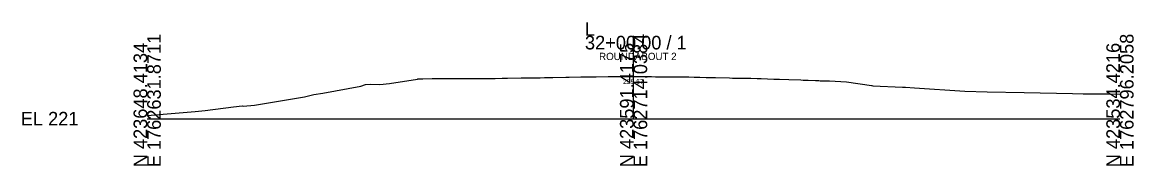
# Model space of a CAD drawing. Extents: x -26 to 3203, y -11010 to 4024.
# Drawn here: x 974.3 to 1202.8, y -3009.7 to -2980.1 of the extents above; entities that cross this region are included whole.
import ezdxf

# ---------------------------------------------------------------- set-up
doc = ezdxf.new("R2010")
doc.units = 0
for name, color, linetype in [('Default', 7, 'Continuous'), ('Exist Cross Section Cell', 7, 'Continuous'), ('Exist XS Center Line Elevation Label', 7, 'Continuous'), ('Exist XS Ground Line', 7, 'Continuous'), ('Prop XS SE Text', 7, 'Continuous')]:
    doc.layers.add(name, color=color, linetype=linetype)

msp = doc.modelspace()

# ---------------------------------------------------------------- linework, layer by layer
at = {"layer": 'Exist Cross Section Cell'}
for p, q in [((1100, -3000), (1100, -2982.95)), ((1000, -3000), (1100, -3000)), ((1100, -3000), (1200, -3000))]:
    msp.add_line(p, q, dxfattribs=at)
at = {"layer": 'Exist XS Ground Line'}
msp.add_lwpolyline([(1000, -2999.32), (1009.89, -2998.55), (1011.89, -2998.34), (1017.75, -2997.59), (1019.55, -2997.35), (1019.72, -2997.44), (1022.06, -2997.21), (1032.31, -2995.53), (1034.23, -2995.04), (1036.12, -2994.75), (1043.89, -2993.34), (1044.91, -2992.97), (1045.93, -2992.89), (1047.82, -2992.94), (1049.85, -2992.74), (1055.59, -2991.84), (1055.61, -2991.82), (1055.64, -2991.82), (1055.83, -2991.81), (1056.18, -2991.79), (1056.69, -2991.79), (1058.59, -2991.76), (1059.08, -2991.76), (1059.14, -2991.76), (1059.72, -2991.75), (1061.04, -2991.75), (1061.93, -2991.74), (1062.83, -2991.74), (1064.17, -2991.74), (1064.98, -2991.74), (1066.77, -2991.73), (1068, -2991.73), (1068.23, -2991.73), (1068.55, -2991.73), (1070.73, -2991.72), (1071.21, -2991.72), (1071.53, -2991.71), (1072.99, -2991.68), (1074.08, -2991.66), (1076.92, -2991.61), (1077.21, -2991.61), (1077.33, -2991.61), (1080.13, -2991.58), (1080.79, -2991.57), (1081.68, -2991.55), (1082.7, -2991.53), (1082.93, -2991.53), (1083.41, -2991.52), (1086.04, -2991.48), (1086.19, -2991.48), (1086.29, -2991.48), (1086.77, -2991.47), (1089.19, -2991.42), (1089.69, -2991.41), (1090.45, -2991.4), (1091.58, -2991.38), (1092.31, -2991.37), (1094.76, -2991.33), (1095.1, -2991.33), (1095.36, -2991.33), (1096.93, -2991.33), (1098.46, -2991.33), (1099.27, -2991.33), (1101.49, -2991.34), (1102.34, -2991.34), (1103.68, -2991.35), (1104.54, -2991.36), (1106.64, -2991.38), (1107.63, -2991.4), (1107.81, -2991.4), (1108.04, -2991.4), (1110.62, -2991.42), (1111.36, -2991.42), (1112.45, -2991.44), (1113.63, -2991.46), (1114.9, -2991.5), (1116.72, -2991.53), (1116.86, -2991.53), (1119.73, -2991.62), (1120.32, -2991.64), (1121.16, -2991.66), (1122.07, -2991.68), (1122.71, -2991.69), (1123.52, -2991.69), (1124.09, -2991.69), (1124.1, -2991.69), (1125.39, -2991.73), (1125.74, -2991.75), (1125.81, -2991.75), (1126.22, -2991.76), (1128.82, -2991.85), (1129.28, -2991.87), (1129.99, -2991.89), (1131.91, -2991.95), (1134.37, -2992.04), (1134.88, -2992.06), (1135.92, -2992.09), (1137.42, -2992.14), (1137.72, -2992.15), (1138.07, -2992.17), (1138.39, -2992.19), (1140.25, -2992.23), (1143.77, -2992.41), (1148.95, -2993.19), (1148.96, -2993.19), (1148.99, -2993.2), (1149.18, -2993.22), (1155.27, -2993.53), (1155.94, -2993.5), (1157.78, -2993.63), (1168.11, -2994.35), (1172.67, -2994.48), (1180.28, -2994.62), (1190.21, -2994.84), (1192.45, -2994.89), (1197.51, -2994.92), (1200, -2994.93)], dxfattribs=at)
msp.add_lwpolyline([(1000, -2999.32), (1009.89, -2998.55), (1011.89, -2998.34), (1017.75, -2997.59), (1019.55, -2997.35), (1019.72, -2997.44), (1022.06, -2997.21), (1032.31, -2995.53), (1034.23, -2995.04), (1036.12, -2994.75), (1043.89, -2993.34), (1044.91, -2992.97), (1045.93, -2992.89), (1047.82, -2992.94), (1049.85, -2992.74), (1055.59, -2991.84), (1055.61, -2991.82), (1055.64, -2991.82), (1055.83, -2991.81), (1056.18, -2991.79), (1056.69, -2991.79), (1058.59, -2991.76), (1059.08, -2991.76), (1059.14, -2991.76), (1059.72, -2991.75), (1061.04, -2991.75), (1061.93, -2991.74), (1062.83, -2991.74), (1064.17, -2991.74), (1064.98, -2991.74), (1066.77, -2991.73), (1068, -2991.73), (1068.23, -2991.73), (1068.55, -2991.73), (1070.73, -2991.72), (1071.21, -2991.72), (1071.53, -2991.71), (1072.99, -2991.68), (1074.08, -2991.66), (1076.92, -2991.61), (1077.21, -2991.61), (1077.33, -2991.61), (1080.13, -2991.58), (1080.79, -2991.57), (1081.68, -2991.55), (1082.7, -2991.53), (1082.93, -2991.53), (1083.41, -2991.52), (1086.04, -2991.48), (1086.19, -2991.48), (1086.29, -2991.48), (1086.77, -2991.47), (1089.19, -2991.42), (1089.69, -2991.41), (1090.45, -2991.4), (1091.58, -2991.38), (1092.31, -2991.37), (1094.76, -2991.33), (1095.1, -2991.33), (1095.36, -2991.33), (1096.93, -2991.33), (1098.46, -2991.33), (1099.27, -2991.33), (1101.49, -2991.34), (1102.34, -2991.34), (1103.68, -2991.35), (1104.54, -2991.36), (1106.64, -2991.38), (1107.63, -2991.4), (1107.81, -2991.4), (1108.04, -2991.4), (1110.62, -2991.42), (1111.36, -2991.42), (1112.45, -2991.44), (1113.63, -2991.46), (1114.9, -2991.5), (1116.72, -2991.53), (1116.86, -2991.53), (1119.73, -2991.62), (1120.32, -2991.64), (1121.16, -2991.66), (1122.07, -2991.68), (1122.71, -2991.69), (1123.52, -2991.69), (1124.09, -2991.69), (1124.1, -2991.69), (1125.39, -2991.73), (1125.74, -2991.75), (1125.81, -2991.75), (1126.22, -2991.76), (1128.82, -2991.85), (1129.28, -2991.87), (1129.99, -2991.89), (1131.91, -2991.95), (1134.37, -2992.04), (1134.88, -2992.06), (1135.92, -2992.09), (1137.42, -2992.14), (1137.72, -2992.15), (1138.07, -2992.17), (1138.39, -2992.19), (1140.25, -2992.23), (1143.77, -2992.41), (1148.95, -2993.19), (1148.96, -2993.19), (1148.99, -2993.2), (1149.18, -2993.22), (1155.27, -2993.53), (1155.94, -2993.5), (1157.78, -2993.63), (1168.11, -2994.35), (1172.67, -2994.48), (1180.28, -2994.62), (1190.21, -2994.84), (1192.45, -2994.89), (1197.51, -2994.92), (1200, -2994.93)], dxfattribs=at)
msp.add_lwpolyline([(1000, -2999.32), (1009.89, -2998.55), (1011.89, -2998.34), (1017.75, -2997.59), (1019.55, -2997.35), (1019.72, -2997.44), (1022.06, -2997.21), (1032.31, -2995.53), (1034.23, -2995.04), (1036.12, -2994.75), (1043.89, -2993.34), (1044.91, -2992.97), (1045.93, -2992.89), (1047.82, -2992.94), (1049.85, -2992.74), (1055.59, -2991.84), (1055.61, -2991.82), (1055.64, -2991.82), (1055.83, -2991.81), (1056.18, -2991.79), (1056.69, -2991.79), (1058.59, -2991.76), (1059.08, -2991.76), (1059.14, -2991.76), (1059.72, -2991.75), (1061.04, -2991.75), (1061.93, -2991.74), (1062.83, -2991.74), (1064.17, -2991.74), (1064.98, -2991.74), (1066.77, -2991.73), (1068, -2991.73), (1068.23, -2991.73), (1068.55, -2991.73), (1070.73, -2991.72), (1071.21, -2991.72), (1071.53, -2991.71), (1072.99, -2991.68), (1074.08, -2991.66), (1076.92, -2991.61), (1077.21, -2991.61), (1077.33, -2991.61), (1080.13, -2991.58), (1080.79, -2991.57), (1081.68, -2991.55), (1082.7, -2991.53), (1082.93, -2991.53), (1083.41, -2991.52), (1086.04, -2991.48), (1086.19, -2991.48), (1086.29, -2991.48), (1086.77, -2991.47), (1089.19, -2991.42), (1089.69, -2991.41), (1090.45, -2991.4), (1091.58, -2991.38), (1092.31, -2991.37), (1094.76, -2991.33), (1095.1, -2991.33), (1095.36, -2991.33), (1096.93, -2991.33), (1098.46, -2991.33), (1099.27, -2991.33), (1101.49, -2991.34), (1102.34, -2991.34), (1103.68, -2991.35), (1104.54, -2991.36), (1106.64, -2991.38), (1107.63, -2991.4), (1107.81, -2991.4), (1108.04, -2991.4), (1110.62, -2991.42), (1111.36, -2991.42), (1112.45, -2991.44), (1113.63, -2991.46), (1114.9, -2991.5), (1116.72, -2991.53), (1116.86, -2991.53), (1119.73, -2991.62), (1120.32, -2991.64), (1121.16, -2991.66), (1122.07, -2991.68), (1122.71, -2991.69), (1123.52, -2991.69), (1124.09, -2991.69), (1124.1, -2991.69), (1125.39, -2991.73), (1125.74, -2991.75), (1125.81, -2991.75), (1126.22, -2991.76), (1128.82, -2991.85), (1129.28, -2991.87), (1129.99, -2991.89), (1131.91, -2991.95), (1134.37, -2992.04), (1134.88, -2992.06), (1135.92, -2992.09), (1137.42, -2992.14), (1137.72, -2992.15), (1138.07, -2992.17), (1138.39, -2992.19), (1140.25, -2992.23), (1143.77, -2992.41), (1148.95, -2993.19), (1148.96, -2993.19), (1148.99, -2993.2), (1149.18, -2993.22), (1155.27, -2993.53), (1155.94, -2993.5), (1157.78, -2993.63), (1168.11, -2994.35), (1172.67, -2994.48), (1180.28, -2994.62), (1190.21, -2994.84), (1192.45, -2994.89), (1197.51, -2994.92), (1200, -2994.93)], dxfattribs=at)
msp.add_lwpolyline([(1000, -2999.32), (1009.89, -2998.55), (1011.89, -2998.34), (1017.75, -2997.59), (1019.55, -2997.35), (1019.72, -2997.44), (1022.06, -2997.21), (1032.31, -2995.53), (1034.23, -2995.04), (1036.12, -2994.75), (1043.89, -2993.34), (1044.91, -2992.97), (1045.93, -2992.89), (1047.82, -2992.94), (1049.85, -2992.74), (1055.59, -2991.84), (1055.61, -2991.82), (1055.64, -2991.82), (1055.83, -2991.81), (1056.18, -2991.79), (1056.69, -2991.79), (1058.59, -2991.76), (1059.08, -2991.76), (1059.14, -2991.76), (1059.72, -2991.75), (1061.04, -2991.75), (1061.93, -2991.74), (1062.83, -2991.74), (1064.17, -2991.74), (1064.98, -2991.74), (1066.77, -2991.73), (1068, -2991.73), (1068.23, -2991.73), (1068.55, -2991.73), (1070.73, -2991.72), (1071.21, -2991.72), (1071.53, -2991.71), (1072.99, -2991.68), (1074.08, -2991.66), (1076.92, -2991.61), (1077.21, -2991.61), (1077.33, -2991.61), (1080.13, -2991.58), (1080.79, -2991.57), (1081.68, -2991.55), (1082.7, -2991.53), (1082.93, -2991.53), (1083.41, -2991.52), (1086.04, -2991.48), (1086.19, -2991.48), (1086.29, -2991.48), (1086.77, -2991.47), (1089.19, -2991.42), (1089.69, -2991.41), (1090.45, -2991.4), (1091.58, -2991.38), (1092.31, -2991.37), (1094.76, -2991.33), (1095.1, -2991.33), (1095.36, -2991.33), (1096.93, -2991.33), (1098.46, -2991.33), (1099.27, -2991.33), (1101.49, -2991.34), (1102.34, -2991.34), (1103.68, -2991.35), (1104.54, -2991.36), (1106.64, -2991.38), (1107.63, -2991.4), (1107.81, -2991.4), (1108.04, -2991.4), (1110.62, -2991.42), (1111.36, -2991.42), (1112.45, -2991.44), (1113.63, -2991.46), (1114.9, -2991.5), (1116.72, -2991.53), (1116.86, -2991.53), (1119.73, -2991.62), (1120.32, -2991.64), (1121.16, -2991.66), (1122.07, -2991.68), (1122.71, -2991.69), (1123.52, -2991.69), (1124.09, -2991.69), (1124.1, -2991.69), (1125.39, -2991.73), (1125.74, -2991.75), (1125.81, -2991.75), (1126.22, -2991.76), (1128.82, -2991.85), (1129.28, -2991.87), (1129.99, -2991.89), (1131.91, -2991.95), (1134.37, -2992.04), (1134.88, -2992.06), (1135.92, -2992.09), (1137.42, -2992.14), (1137.72, -2992.15), (1138.07, -2992.17), (1138.39, -2992.19), (1140.25, -2992.23), (1143.77, -2992.41), (1148.95, -2993.19), (1148.96, -2993.19), (1148.99, -2993.2), (1149.18, -2993.22), (1155.27, -2993.53), (1155.94, -2993.5), (1157.78, -2993.63), (1168.11, -2994.35), (1172.67, -2994.48), (1180.28, -2994.62), (1190.21, -2994.84), (1192.45, -2994.89), (1197.51, -2994.92), (1200, -2994.93)], dxfattribs=at)
msp.add_lwpolyline([(1000, -2999.32), (1009.89, -2998.55), (1011.89, -2998.34), (1017.75, -2997.59), (1019.55, -2997.35), (1019.72, -2997.44), (1022.06, -2997.21), (1032.31, -2995.53), (1034.23, -2995.04), (1036.12, -2994.75), (1043.89, -2993.34), (1044.91, -2992.97), (1045.93, -2992.89), (1047.82, -2992.94), (1049.85, -2992.74), (1055.59, -2991.84), (1055.61, -2991.82), (1055.64, -2991.82), (1055.83, -2991.81), (1056.18, -2991.79), (1056.69, -2991.79), (1058.59, -2991.76), (1059.08, -2991.76), (1059.14, -2991.76), (1059.72, -2991.75), (1061.04, -2991.75), (1061.93, -2991.74), (1062.83, -2991.74), (1064.17, -2991.74), (1064.98, -2991.74), (1066.77, -2991.73), (1068, -2991.73), (1068.23, -2991.73), (1068.55, -2991.73), (1070.73, -2991.72), (1071.21, -2991.72), (1071.53, -2991.71), (1072.99, -2991.68), (1074.08, -2991.66), (1076.92, -2991.61), (1077.21, -2991.61), (1077.33, -2991.61), (1080.13, -2991.58), (1080.79, -2991.57), (1081.68, -2991.55), (1082.7, -2991.53), (1082.93, -2991.53), (1083.41, -2991.52), (1086.04, -2991.48), (1086.19, -2991.48), (1086.29, -2991.48), (1086.77, -2991.47), (1089.19, -2991.42), (1089.69, -2991.41), (1090.45, -2991.4), (1091.58, -2991.38), (1092.31, -2991.37), (1094.76, -2991.33), (1095.1, -2991.33), (1095.36, -2991.33), (1096.93, -2991.33), (1098.46, -2991.33), (1099.27, -2991.33), (1101.49, -2991.34), (1102.34, -2991.34), (1103.68, -2991.35), (1104.54, -2991.36), (1106.64, -2991.38), (1107.63, -2991.4), (1107.81, -2991.4), (1108.04, -2991.4), (1110.62, -2991.42), (1111.36, -2991.42), (1112.45, -2991.44), (1113.63, -2991.46), (1114.9, -2991.5), (1116.72, -2991.53), (1116.86, -2991.53), (1119.73, -2991.62), (1120.32, -2991.64), (1121.16, -2991.66), (1122.07, -2991.68), (1122.71, -2991.69), (1123.52, -2991.69), (1124.09, -2991.69), (1124.1, -2991.69), (1125.39, -2991.73), (1125.74, -2991.75), (1125.81, -2991.75), (1126.22, -2991.76), (1128.82, -2991.85), (1129.28, -2991.87), (1129.99, -2991.89), (1131.91, -2991.95), (1134.37, -2992.04), (1134.88, -2992.06), (1135.92, -2992.09), (1137.42, -2992.14), (1137.72, -2992.15), (1138.07, -2992.17), (1138.39, -2992.19), (1140.25, -2992.23), (1143.77, -2992.41), (1148.95, -2993.19), (1148.96, -2993.19), (1148.99, -2993.2), (1149.18, -2993.22), (1155.27, -2993.53), (1155.94, -2993.5), (1157.78, -2993.63), (1168.11, -2994.35), (1172.67, -2994.48), (1180.28, -2994.62), (1190.21, -2994.84), (1192.45, -2994.89), (1197.51, -2994.92), (1200, -2994.93)], dxfattribs=at)

# ---------------------------------------------------------------- texts
at = {"layer": 'Default'}
msp.add_text('-', height=0.0001, dxfattribs=at).set_placement((1000, -3000))
msp.add_text('-', height=0.0001, dxfattribs=at).set_placement((1000, -3000))
at = {"layer": 'Exist Cross Section Cell'}
for s, p in [('L', (1090, -2982.95)), ('32+00.00 / 1', (1090, -2985.75)), ('EL 221', (974, -3001.4))]:
    msp.add_text(s, height=2.8, dxfattribs=at).set_placement(p)
for s, p in [('N 423648.4134', (1000, -3010)), ('E 1762631.8711', (1002.8, -3010)), ('N 423591.4175', (1100, -3010)), ('E 1762714.0384', (1102.8, -3010)), ('N 423534.4216', (1200, -3010)), ('E 1762796.2058', (1202.8, -3010))]:
    msp.add_text(s, height=2.8, rotation=90, dxfattribs=at).set_placement(p)
at = {"layer": 'Exist XS Center Line Elevation Label'}
msp.add_text('229.67', height=1, dxfattribs=at).set_placement((1097.85, -2992.83))
at = {"layer": 'Prop XS SE Text'}
msp.add_text('ROUNDABOUT 2', height=1.5, rotation=360, dxfattribs=at).set_placement((1092.91, -2987.94))

doc.saveas('drawing.dxf')
